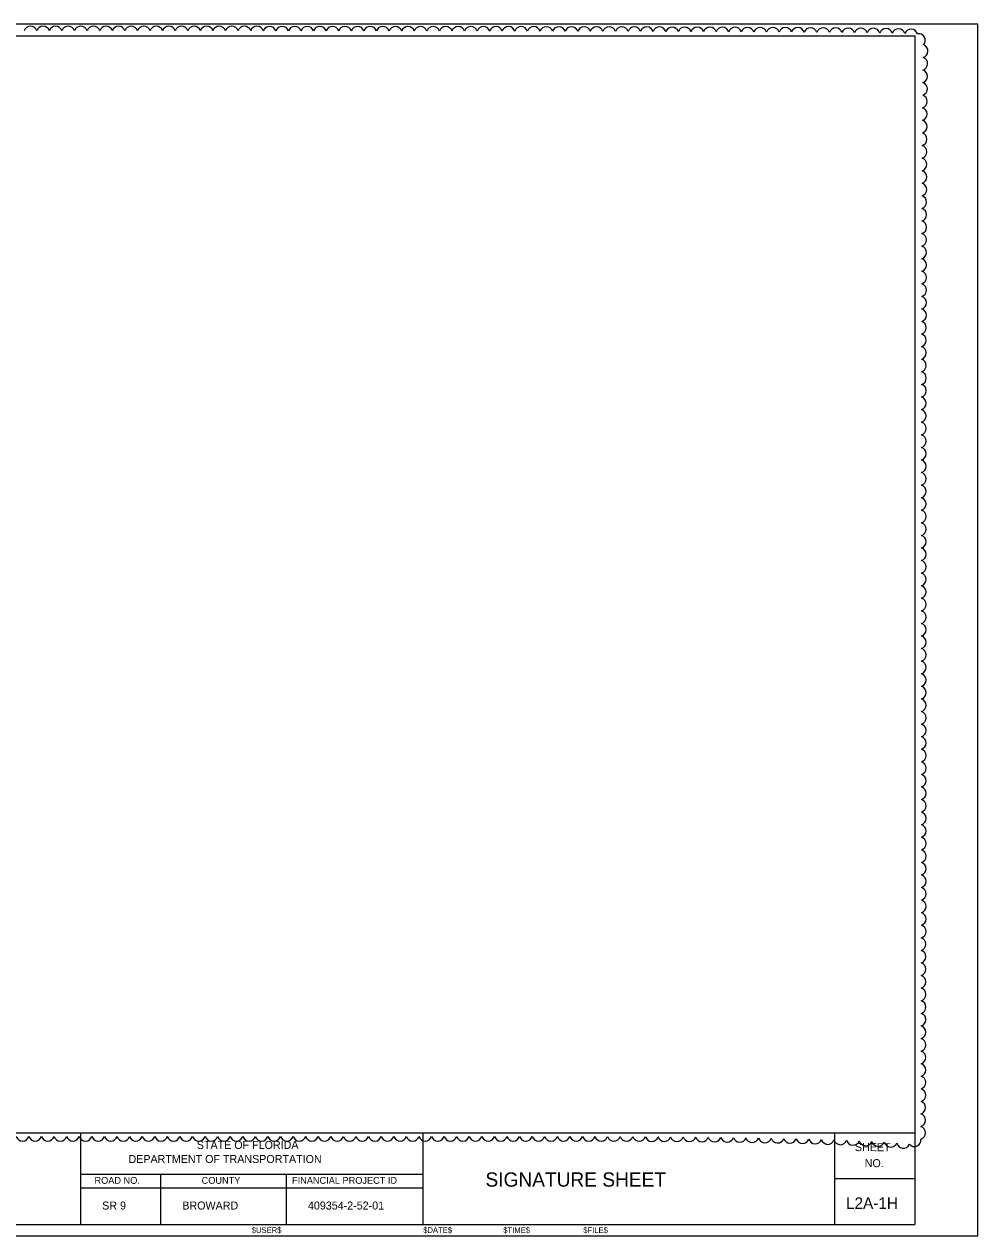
# Model space of a CAD drawing. Extents: x -811 to 10319, y -2309 to 9962.
# Drawn here: x -803.28 to -794.93, y -2297.01 to -2286.41 of the extents above; entities that cross this region are included whole.
import ezdxf

# ---------------------------------------------------------------- set-up
doc = ezdxf.new("R2010")
doc.units = 0
for name, color, linetype in [('PlotBorder_dp', 7, 'Continuous'), ('ScratchEle_dp', 7, 'Continuous'), ('SheetLines_dp', 7, 'Continuous'), ('TextMinor', 7, 'Continuous'), ('TextNotes', 7, 'Continuous')]:
    doc.layers.add(name, color=color, linetype=linetype)

msp = doc.modelspace()

# ---------------------------------------------------------------- linework, layer by layer
at = {"layer": 'PlotBorder_dp'}
msp.add_lwpolyline([(-811.435, -2297.009), (-794.935, -2297.009), (-794.935, -2286.409), (-811.435, -2286.409)], close=True, dxfattribs=at)
at = {"layer": 'ScratchEle_dp'}
for centre, start, end in [((-803.221, -2286.484), 17.5, 162.5), ((-803.111, -2286.484), 17.4999, 162.4999), ((-803.001, -2286.484), 17.4985, 162.4985), ((-802.891, -2286.484), 17.4968, 162.4968), ((-802.781, -2286.484), 17.495, 162.495), ((-802.67, -2286.484), 17.4932, 162.4932), ((-802.56, -2286.484), 17.4913, 162.4913), ((-802.45, -2286.484), 17.4894, 162.4894), ((-802.34, -2286.484), 17.4875, 162.4875), ((-802.23, -2286.484), 17.4855, 162.4855), ((-802.12, -2286.484), 17.4835, 162.4835), ((-802.01, -2286.484), 17.4814, 162.4814), ((-801.9, -2286.484), 17.4792, 162.4792), ((-801.79, -2286.484), 17.477, 162.477), ((-801.68, -2286.484), 17.4748, 162.4748), ((-801.57, -2286.484), 17.4725, 162.4725), ((-801.46, -2286.484), 17.4701, 162.4701), ((-801.35, -2286.484), 17.4676, 162.4676), ((-801.24, -2286.484), 17.4651, 162.4651), ((-801.13, -2286.485), 17.4625, 162.4625), ((-801.02, -2286.485), 17.4599, 162.4599), ((-800.91, -2286.485), 17.4571, 162.4571), ((-800.8, -2286.485), 17.4543, 162.4543), ((-800.69, -2286.485), 17.4514, 162.4514), ((-800.58, -2286.485), 17.4484, 162.4484), ((-800.47, -2286.485), 17.4453, 162.4453), ((-800.36, -2286.485), 17.4421, 162.4421), ((-800.25, -2286.485), 17.4388, 162.4388), ((-800.14, -2286.485), 17.4354, 162.4354), ((-800.029, -2286.486), 17.4318, 162.4318), ((-799.919, -2286.486), 17.4281, 162.4281), ((-799.809, -2286.486), 17.4243, 162.4243), ((-799.699, -2286.486), 17.4204, 162.4204), ((-799.589, -2286.486), 17.4162, 162.4162), ((-799.479, -2286.486), 17.412, 162.412), ((-799.369, -2286.486), 17.4075, 162.4075), ((-799.259, -2286.487), 17.4029, 162.4029), ((-799.149, -2286.487), 17.398, 162.398), ((-799.039, -2286.487), 17.3929, 162.3929), ((-798.929, -2286.487), 17.3876, 162.3876), ((-798.819, -2286.487), 17.3821, 162.3821), ((-798.709, -2286.488), 17.3762, 162.3762), ((-798.599, -2286.488), 17.3701, 162.3701), ((-798.489, -2286.488), 17.3636, 162.3636), ((-798.379, -2286.488), 17.3568, 162.3568), ((-798.269, -2286.489), 17.3496, 162.3496), ((-798.159, -2286.489), 17.342, 162.342), ((-798.049, -2286.489), 17.3339, 162.3339), ((-797.939, -2286.49), 17.3253, 162.3253), ((-797.829, -2286.49), 17.3161, 162.3161), ((-797.719, -2286.49), 17.3062, 162.3062), ((-797.609, -2286.491), 17.2956, 162.2956), ((-797.499, -2286.491), 17.2842, 162.2842), ((-797.388, -2286.492), 17.2719, 162.2719), ((-797.278, -2286.492), 17.2584, 162.2584), ((-797.168, -2286.493), 17.2438, 162.2438), ((-797.058, -2286.493), 17.2277, 162.2277), ((-796.948, -2286.494), 17.2099, 162.2099), ((-796.838, -2286.494), 17.1901, 162.1901), ((-796.728, -2286.495), 17.1679, 162.1679), ((-796.618, -2286.495), 17.1427, 162.1427), ((-796.508, -2286.496), 17.1138, 162.1138), ((-796.398, -2286.497), 17.0803, 162.0803), ((-796.288, -2286.498), 17.0406, 162.0406), ((-796.178, -2286.499), 16.9927, 161.9927), ((-796.068, -2286.5), 16.9334, 161.9334), ((-795.958, -2286.501), 16.857, 161.857), ((-795.848, -2286.502), 16.7534, 161.7534), ((-795.738, -2286.504), 16.6013, 161.6013), ((-795.628, -2286.506), 16.3442, 161.3442), ((-795.518, -2286.509), 15.7356, 160.7356), ((-795.451, -2286.549), 316.2708, 101.2708), ((-795.428, -2286.644), 286.1724, 71.1724), ((-795.431, -2286.754), 286.5791, 71.5791), ((-795.432, -2286.864), 286.7773, 71.7773), ((-795.433, -2286.974), 286.9008, 71.9008), ((-795.434, -2287.084), 286.9872, 71.9872), ((-795.435, -2287.194), 287.0522, 72.0522), ((-795.436, -2287.304), 287.1032, 72.1032), ((-795.437, -2287.415), 287.1448, 72.1448), ((-795.438, -2287.525), 287.1794, 72.1794), ((-795.438, -2287.635), 287.2089, 72.2089), ((-795.439, -2287.745), 287.2343, 72.2343), ((-795.439, -2287.855), 287.2566, 72.2566), ((-795.44, -2287.965), 287.2764, 72.2764), ((-795.44, -2288.075), 287.294, 72.294), ((-795.44, -2288.185), 287.3099, 72.3099), ((-795.441, -2288.295), 287.3243, 72.3243), ((-795.441, -2288.405), 287.3374, 72.3374), ((-795.441, -2288.515), 287.3494, 72.3494), ((-795.442, -2288.625), 287.3605, 72.3605), ((-795.442, -2288.735), 287.3708, 72.3708), ((-795.442, -2288.845), 287.3803, 72.3803), ((-795.442, -2288.955), 287.3892, 72.3892), ((-795.443, -2289.065), 287.3975, 72.3975), ((-795.443, -2289.175), 287.4053, 72.4053), ((-795.443, -2289.285), 287.4126, 72.4126), ((-795.443, -2289.395), 287.4195, 72.4195), ((-795.443, -2289.505), 287.426, 72.426), ((-795.443, -2289.615), 287.4322, 72.4322), ((-795.444, -2289.725), 287.438, 72.438), ((-795.444, -2289.836), 287.4436, 72.4436), ((-795.444, -2289.946), 287.4489, 72.4489), ((-795.444, -2290.056), 287.4539, 72.4539), ((-795.444, -2290.166), 287.4588, 72.4588), ((-795.444, -2290.276), 287.4634, 72.4634), ((-795.444, -2290.386), 287.4678, 72.4678), ((-795.444, -2290.496), 287.472, 72.472), ((-795.444, -2290.606), 287.476, 72.476), ((-795.444, -2290.716), 287.4799, 72.4799), ((-795.444, -2290.826), 287.4837, 72.4837), ((-795.444, -2290.936), 287.4873, 72.4873), ((-795.444, -2291.046), 287.4907, 72.4907), ((-795.444, -2291.156), 287.4941, 72.4941), ((-795.444, -2291.266), 287.4973, 72.4973), ((-795.444, -2291.376), 287.4996, 72.4996), ((-795.444, -2291.486), 287.4988, 72.4988), ((-795.444, -2291.596), 287.4977, 72.4977), ((-795.444, -2291.706), 287.4966, 72.4966), ((-795.444, -2291.816), 287.4954, 72.4954), ((-795.444, -2291.926), 287.4942, 72.4942), ((-795.444, -2292.036), 287.4929, 72.4929), ((-795.444, -2292.146), 287.4916, 72.4916), ((-795.444, -2292.257), 287.4903, 72.4903), ((-795.444, -2292.367), 287.4888, 72.4888), ((-795.444, -2292.477), 287.4874, 72.4874), ((-795.445, -2292.587), 287.4858, 72.4858), ((-795.445, -2292.697), 287.4842, 72.4842), ((-795.445, -2292.807), 287.4825, 72.4825), ((-795.445, -2292.917), 287.4807, 72.4807), ((-795.445, -2293.027), 287.4788, 72.4788), ((-795.445, -2293.137), 287.4768, 72.4768), ((-795.445, -2293.247), 287.4747, 72.4747), ((-795.445, -2293.357), 287.4725, 72.4725), ((-795.445, -2293.467), 287.4702, 72.4702), ((-795.445, -2293.577), 287.4677, 72.4677), ((-795.445, -2293.687), 287.4651, 72.4651), ((-795.445, -2293.797), 287.4622, 72.4622), ((-795.445, -2293.907), 287.4592, 72.4592), ((-795.445, -2294.017), 287.456, 72.456), ((-795.445, -2294.127), 287.4525, 72.4525), ((-795.445, -2294.237), 287.4487, 72.4487), ((-795.445, -2294.347), 287.4446, 72.4446), ((-795.446, -2294.457), 287.4401, 72.4401), ((-795.446, -2294.567), 287.4351, 72.4351), ((-795.446, -2294.677), 287.4296, 72.4296), ((-795.446, -2294.788), 287.4236, 72.4236), ((-795.446, -2294.898), 287.4167, 72.4167), ((-795.446, -2295.008), 287.409, 72.409), ((-795.446, -2295.118), 287.4001, 72.4001), ((-795.447, -2295.228), 287.3897, 72.3897), ((-795.447, -2295.338), 287.3775, 72.3775), ((-795.447, -2295.448), 287.3627, 72.3627), ((-795.447, -2295.558), 287.3443, 72.3443), ((-795.448, -2295.668), 287.3206, 72.3206), ((-795.448, -2295.778), 287.2884, 72.2884), ((-795.449, -2295.888), 287.2408, 72.2408), ((-795.449, -2295.998), 287.1595, 72.1595), ((-795.45, -2296.108), 286.9603, 71.9603), ((-803.29, -2296.122), 197.5, 342.5), ((-803.18, -2296.122), 197.5, 342.5), ((-803.07, -2296.122), 197.5, 342.5), ((-802.96, -2296.122), 197.5, 342.5), ((-802.85, -2296.122), 197.5, 342.5), ((-802.739, -2296.122), 197.5, 342.5), ((-802.629, -2296.122), 197.5, 342.5), ((-802.519, -2296.122), 197.5, 342.5), ((-802.409, -2296.122), 197.5, 342.5), ((-802.299, -2296.122), 197.5, 342.5), ((-802.189, -2296.122), 197.5, 342.5), ((-802.079, -2296.122), 197.5, 342.5), ((-801.969, -2296.122), 197.5, 342.5), ((-801.859, -2296.122), 197.5, 342.5), ((-801.749, -2296.122), 197.5, 342.5), ((-801.639, -2296.122), 197.5, 342.5), ((-801.529, -2296.122), 197.5, 342.5), ((-801.419, -2296.122), 197.5, 342.5), ((-801.309, -2296.122), 197.5, 342.5), ((-801.199, -2296.122), 197.5, 342.5), ((-801.089, -2296.122), 197.5, 342.5), ((-800.979, -2296.122), 197.5, 342.5), ((-800.869, -2296.122), 197.5, 342.5), ((-800.759, -2296.122), 197.5, 342.5), ((-800.649, -2296.122), 197.5, 342.5), ((-800.539, -2296.122), 197.5, 342.5), ((-800.429, -2296.122), 197.5, 342.5), ((-800.319, -2296.122), 197.5, 342.5), ((-800.208, -2296.122), 197.5, 342.5), ((-800.098, -2296.122), 197.5, 342.5), ((-799.988, -2296.122), 197.5, 342.5), ((-799.878, -2296.122), 197.5, 342.5), ((-799.768, -2296.122), 197.5, 342.5), ((-799.658, -2296.122), 197.5, 342.5), ((-799.548, -2296.122), 197.5, 342.5), ((-799.438, -2296.122), 197.5, 342.5), ((-799.328, -2296.122), 197.5, 342.5), ((-799.218, -2296.122), 197.5, 342.5), ((-799.108, -2296.122), 197.5, 342.5), ((-798.998, -2296.122), 197.5, 342.5), ((-798.888, -2296.122), 197.5, 342.5), ((-798.778, -2296.122), 197.5, 342.5), ((-798.668, -2296.122), 197.5, 342.5), ((-798.558, -2296.122), 197.4875, 342.4875), ((-798.448, -2296.122), 197.4461, 342.4461), ((-798.338, -2296.122), 197.4016, 342.4016), ((-798.228, -2296.123), 197.3547, 342.3547), ((-798.118, -2296.123), 197.3053, 342.3053), ((-798.008, -2296.123), 197.2532, 342.2532), ((-797.897, -2296.124), 197.198, 342.198), ((-797.787, -2296.125), 197.1394, 342.1394), ((-797.677, -2296.125), 197.0771, 342.0771), ((-797.567, -2296.126), 197.0107, 342.0107), ((-797.457, -2296.127), 196.9397, 341.9397), ((-797.347, -2296.128), 196.8636, 341.8636), ((-797.237, -2296.13), 196.7816, 341.7816), ((-797.127, -2296.131), 196.6931, 341.6931), ((-797.017, -2296.133), 196.597, 341.597), ((-796.907, -2296.135), 196.4924, 341.4924), ((-796.797, -2296.137), 196.3777, 341.3777), ((-796.687, -2296.139), 196.2513, 341.2513), ((-796.577, -2296.141), 196.111, 341.111), ((-796.467, -2296.144), 195.9541, 340.9541), ((-796.357, -2296.147), 195.8088, 340.8088), ((-796.247, -2296.151), 195.6685, 340.6685), ((-796.137, -2296.154), 195.4928, 340.4928), ((-795.49, -2296.17), 222.0186, 7.0186), ((-796.027, -2296.159), 195.2636, 340.2636), ((-795.916, -2296.163), 194.9466, 339.9466), ((-795.806, -2296.169), 194.4656, 339.4656), ((-795.696, -2296.175), 193.5975, 338.5975), ((-795.586, -2296.185), 190.9865, 335.9865)]:
    msp.add_arc(centre, 0.0577, start, end, dxfattribs=at)
at = {"layer": 'SheetLines_dp'}
for p, q in [((-802.785, -2296.109), (-802.785, -2296.909)), ((-799.785, -2296.909), (-799.785, -2296.109)), ((-796.185, -2296.909), (-796.185, -2296.109)), ((-802.785, -2296.469), (-799.785, -2296.469)), ((-802.085, -2296.469), (-802.085, -2296.909)), ((-800.985, -2296.469), (-800.985, -2296.909)), ((-802.785, -2296.589), (-799.785, -2296.589)), ((-796.185, -2296.509), (-795.485, -2296.509))]:
    msp.add_line(p, q, dxfattribs=at)
at = {"layer": 'TextNotes'}
for p, q in [((-810.885, -2286.509), (-795.485, -2286.509)), ((-795.485, -2286.509), (-795.485, -2296.909)), ((-810.885, -2296.109), (-795.485, -2296.109)), ((-810.885, -2296.909), (-795.485, -2296.909))]:
    msp.add_line(p, q, dxfattribs=at)

# ---------------------------------------------------------------- texts
at = {"layer": 'PlotBorder_dp'}
for s, height, p in [('STATE OF FLORIDA', 0.07, (-801.766, -2296.249)), ('DEPARTMENT OF TRANSPORTATION', 0.07, (-802.364, -2296.372)), ('       SIGNATURE SHEET         ', 0.125, (-799.566, -2296.579)), ('ROAD NO.', 0.06, (-802.661, -2296.554)), ('COUNTY', 0.06, (-801.724, -2296.554)), ('FINANCIAL PROJECT ID', 0.06, (-800.933, -2296.554)), (' SR 9  ', 0.07, (-802.62, -2296.779)), ('  BROWARD   ', 0.07, (-801.945, -2296.779)), ('409354-2-52-01', 0.07, (-800.794, -2296.779))]:
    msp.add_text(s, height=height, dxfattribs=at).set_placement(p)
for s, p in [('SHEET', (-796.01, -2296.268)), ('NO.', (-795.924, -2296.408))]:
    msp.add_text(s, height=0.07, rotation=359.8607, dxfattribs=at).set_placement(p)
at = {"layer": 'SheetLines_dp'}
msp.add_text('L2A-1H', height=0.1, dxfattribs=at).set_placement((-796.087, -2296.773))
at = {"layer": 'TextMinor'}
msp.add_text('$USER$', height=0.05, dxfattribs=at).set_placement((-801.286, -2296.984))
for s, p in [('$DATE$', (-799.786, -2296.984)), ('$TIME$', (-799.086, -2296.984)), ('$FILE$', (-798.386, -2296.984))]:
    msp.add_text(s, height=0.05, rotation=360, dxfattribs=at).set_placement(p)

doc.saveas('drawing.dxf')
